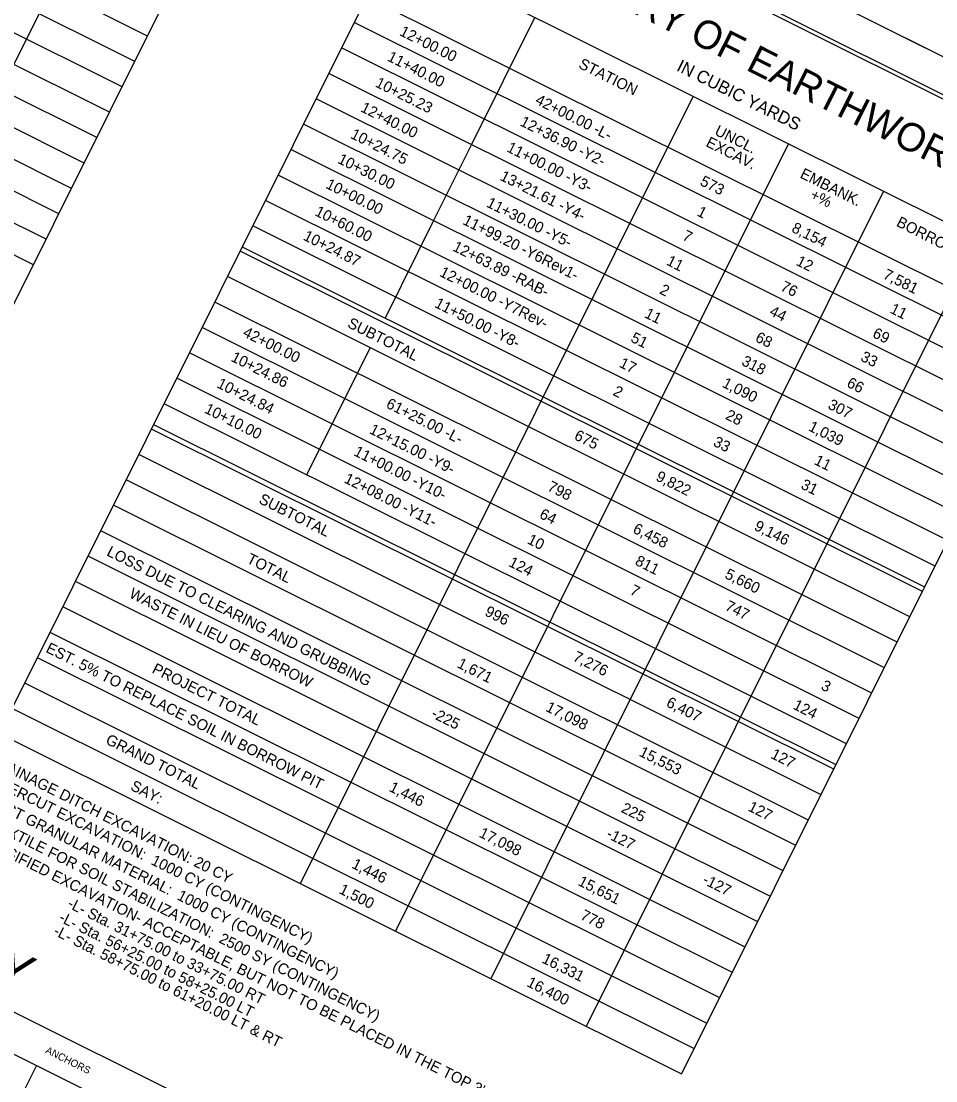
# Model space of a CAD drawing. Extents: x 1771109 to 1774678, y 884436 to 887277.
# Drawn here: x 1773772 to 1774376, y 885998 to 886698 of the extents above; entities that cross this region are included whole.
import ezdxf

# ---------------------------------------------------------------- set-up
doc = ezdxf.new("R2010")
doc.units = 0
for name, color, linetype in [('Sheet Border Standard 30in CELL', 7, 'Continuous'), ('Sheet Cutting Line CELL', 7, 'Continuous'), ('Sheet Plot Border Inside CELL', 7, 'Continuous'), ('Sheet Plot Border Outside CELL', 7, 'Continuous'), ('Sheet Summary Combination CELL', 7, 'Continuous'), ('Sheet Summary Combination Grid CELL', 7, 'Continuous'), ('Sheet Summary Earthwork CELL', 7, 'Continuous'), ('Sheet Summary Guardrail CELL', 7, 'Continuous')]:
    doc.layers.add(name, color=color, linetype=linetype)

msp = doc.modelspace()

# ---------------------------------------------------------------- linework, layer by layer
at = {"layer": 'Sheet Border Standard 30in CELL'}
msp.add_lwpolyline([(1774652.12, 886510.92), (1773309.73, 887180.24), (1772841.21, 886240.56), (1774183.6, 885571.25)], close=True, dxfattribs=at)
at = {"layer": 'Sheet Cutting Line CELL'}
msp.add_line((1774678.49, 886525.71), (1773171.43, 887277.13), dxfattribs=at)
at = {"layer": 'Sheet Plot Border Inside CELL'}
msp.add_lwpolyline([(1774664.45, 886507.63), (1773173.05, 887251.23), (1772702.25, 886307), (1774193.65, 885563.39)], close=True, dxfattribs=at)
at = {"layer": 'Sheet Plot Border Outside CELL'}
msp.add_lwpolyline([(1774678.49, 886525.71), (1773171.43, 887277.13), (1772680.6, 886292.7), (1774187.66, 885541.29)], close=True, dxfattribs=at)
at = {"layer": 'Sheet Summary Combination CELL'}
for p, q in [((1774153.09, 886679.28), (1774153.09, 886679.28)), ((1774161.42, 886674.96), (1774161.42, 886674.96)), ((1774173.7, 886669.17), (1774173.7, 886669.17)), ((1774181.15, 886665.29), (1774181.15, 886665.29))]:
    msp.add_line(p, q, dxfattribs=at)
at = {"layer": 'Sheet Summary Combination Grid CELL'}
for p, q in [((1773287.9, 886970.94), (1773854.86, 886688.25)), ((1773279.53, 886954.16), (1773846.49, 886671.47)), ((1773271.17, 886937.38), (1773838.13, 886654.69)), ((1773262.8, 886920.6), (1773829.76, 886637.91)), ((1773254.44, 886903.82), (1773821.4, 886621.13)), ((1773246.07, 886887.04), (1773813.03, 886604.35)), ((1773237.7, 886870.26), (1773804.66, 886587.57)), ((1773229.34, 886853.48), (1773796.3, 886570.79)), ((1773220.97, 886836.7), (1773787.93, 886554.01)), ((1773212.6, 886819.92), (1773779.56, 886537.23)), ((1773833.6, 886803.61), (1773607.71, 886350.55)), ((1773896.69, 886772.15), (1773670.8, 886319.09)), ((1774016.48, 886747.48), (1773757.12, 886227.3)), ((1774016.48, 886747.48), (1774467.11, 886522.79)), ((1773999.74, 886713.92), (1774450.38, 886489.23)), ((1774110.91, 886700.39), (1774069.08, 886616.49)), ((1773991.38, 886697.14), (1774442.01, 886472.45)), ((1773983.01, 886680.36), (1774433.65, 886455.67)), ((1773974.64, 886663.58), (1774425.28, 886438.89)), ((1774215.28, 886648.36), (1773955.92, 886128.18)), ((1773966.28, 886646.8), (1774416.91, 886422.11)), ((1773957.91, 886630.02), (1774408.55, 886405.33)), ((1774278.24, 886616.97), (1774018.88, 886096.79)), ((1774069.08, 886616.49), (1774043.98, 886566.15)), ((1773949.54, 886613.24), (1774400.18, 886388.55)), ((1773941.18, 886596.46), (1774391.81, 886371.77)), ((1774341.2, 886585.57), (1774081.84, 886065.4)), ((1773932.81, 886579.68), (1774383.45, 886354.99)), ((1773924.44, 886562.9), (1774375.08, 886338.21)), ((1774043.98, 886566.15), (1774011.89, 886501.79)), ((1774404.15, 886554.18), (1774144.79, 886034.01)), ((1773917.46, 886548.88), (1774368.09, 886324.19)), ((1773916.08, 886546.12), (1774366.72, 886321.43)), ((1773907.71, 886529.34), (1774358.35, 886304.65)), ((1774467.11, 886522.79), (1774207.75, 886002.62)), ((1773899.35, 886512.56), (1774349.98, 886287.87)), ((1773890.98, 886495.78), (1774341.62, 886271.09)), ((1773882.61, 886479), (1774333.25, 886254.31)), ((1774002.15, 886482.25), (1773960.32, 886398.35)), ((1773874.25, 886462.22), (1774324.88, 886237.53)), ((1773865.88, 886445.44), (1774316.52, 886220.75)), ((1773857.51, 886428.66), (1774308.15, 886203.97)), ((1773858.97, 886431.58), (1774309.61, 886206.9)), ((1773849.15, 886411.88), (1774299.78, 886187.19)), ((1773840.78, 886395.1), (1774291.42, 886170.41)), ((1773832.41, 886378.32), (1774283.05, 886153.63)), ((1773824.05, 886361.54), (1774274.68, 886136.85)), ((1773815.68, 886344.76), (1774266.32, 886120.07)), ((1773807.32, 886327.98), (1774257.95, 886103.3)), ((1773798.95, 886311.2), (1774249.59, 886086.52)), ((1773790.58, 886294.42), (1774241.22, 886069.74)), ((1773782.22, 886277.64), (1774232.85, 886052.96)), ((1773773.85, 886260.86), (1774224.49, 886036.18)), ((1773765.48, 886244.08), (1774216.12, 886019.4)), ((1773757.12, 886227.3), (1774207.75, 886002.62))]:
    msp.add_line(p, q, dxfattribs=at)
at = {"layer": 'Sheet Summary Guardrail CELL'}
for p, q in [((1772947.61, 886451.91), (1774290, 885782.59)), ((1773928.84, 885934.73), (1773500.7, 886148.2)), ((1773781.62, 886008.13), (1773714.69, 885873.89))]:
    msp.add_line(p, q, dxfattribs=at)

# ---------------------------------------------------------------- texts
at = {"layer": 'Sheet Summary Combination CELL'}
for s, p in [('12+00.00', (1774020.9, 886688.85)), ('11+40.00', (1774012.87, 886672.05)), ('STATION', (1774139.17, 886667.29)), ('10+25.23', (1774004.87, 886654.89)), ('42+00.00 -L-', (1774110.5, 886643.61)), ('12+40.00', (1773995.17, 886638.47)), ('12+36.90 -Y2-', (1774100.46, 886629.2)), ('10+24.75', (1773988.54, 886620.95)), ('UNCL.', (1774229, 886623.16)), ('11+00.00 -Y3-', (1774091.68, 886612.1)), ('EXCAV.', (1774223.21, 886615.5)), ('10+30.00', (1773980.04, 886604.48)), ('13+21.61 -Y4-', (1774087.24, 886593.23)), ('573', (1774219.35, 886589.85)), ('EMBANK.', (1774285.42, 886594.79)), ('10+00.00', (1773972.14, 886587.93)), ('+%', (1774291.99, 886580.92)), ('10+60.00', (1773964.94, 886569.91)), ('11+30.00 -Y5-', (1774078.32, 886575.59)), ('1', (1774217.36, 886569.72)), ('11+99.20 -Y6Rev1-', (1774062.62, 886564.09)), ('BORROW', (1774349.02, 886562.82)), ('8,154', (1774279.82, 886559.03)), ('10+24.87', (1773957.31, 886553.75)), ('7', (1774207.73, 886553.85)), ('12+63.89 -RAB-', (1774055.97, 886546.62)), ('11', (1774197.18, 886537.23)), ('12', (1774282.84, 886537.08)), ('12+00.00 -Y7Rev-', (1774047.3, 886529.83)), ('7,581', (1774340.24, 886528.3)), ('76', (1774272.5, 886520.35)), ('2', (1774192.66, 886518.2)), ('11+50.00 -Y8-', (1774044.01, 886509.26)), ('11', (1774182.7, 886502.5)), ('44', (1774265.14, 886503.96)), ('11', (1774344.83, 886505.56)), ('SUBTOTAL', (1773986.46, 886496.07)), ('42+00.00 ', (1773917.4, 886490.08)), ('51', (1774173.59, 886486.46)), ('68', (1774255.86, 886486.7)), ('69', (1774333.28, 886489.44)), ('10+24.86', (1773909.59, 886473.67)), ('318', (1774246.76, 886471.1)), ('33', (1774325.4, 886473.92)), ('17', (1774165.99, 886469.74)), ('66', (1774316.26, 886456.7)), ('10+24.84', (1773900.25, 886456.25)), ('2', (1774161.88, 886451.18)), ('1,090', (1774234.03, 886456.55)), ('61+25.00 -L-', (1774012.02, 886442.92)), ('10+10.00', (1773892.02, 886439.54)), ('307', (1774303.81, 886442.31)), ('28', (1774236.13, 886435.38)), ('12+15.00 -Y9-', (1774000.99, 886425.95)), ('675', (1774136.26, 886421.96)), ('1,039', (1774290.95, 886427.82)), ('33', (1774228.06, 886417.73)), ('11+00.00 -Y10-', (1773990.67, 886411.39)), ('11', (1774294.78, 886405.51)), ('9,822', (1774190.15, 886394.84)), ('12+08.00 -Y11-', (1773984.23, 886393.43)), ('798', (1774118.58, 886388.19)), ('31', (1774285.94, 886389.49)), ('SUBTOTAL', (1773927.9, 886379.88)), ('64', (1774113.27, 886370.01)), ('6,458', (1774175, 886360.34)), ('9,146', (1774255.11, 886362.18)), ('10', (1774105.25, 886353.17)), ('LOSS DUE TO CLEARING AND GRUBBING', (1773827.51, 886345.24)), ('TOTAL', (1773919.95, 886340.42)), ('124', (1774092.94, 886338.21)), ('811', (1774176.45, 886339.13)), ('5,660', (1774235.71, 886330.38)), ('WASTE IN LIEU OF BORROW', (1773842.34, 886317.57)), ('7', (1774173.04, 886319.7)), ('747', (1774235.9, 886309.3)), ('996', (1774077.2, 886305.71)), ('EST. 5% TO REPLACE SOIL IN BORROW PIT', (1773787.34, 886281.47)), ('7,276', (1774135.41, 886275.84)), ('PROJECT TOTAL', (1773857.47, 886267.8)), ('1,671', (1774058.96, 886271.3)), ('3', (1774299.26, 886256.77)), ('17,098', (1774117.4, 886242.58)), ('6,407', (1774197.04, 886245.6)), ('124', (1774280.77, 886243.93)), ('-225', (1774041.81, 886238.44)), ('GRAND TOTAL', (1773826.8, 886221.01)), ('15,553', (1774179.1, 886212.91)), ('DRAINAGE DITCH EXCAVATION: 20 CY', (1773748.72, 886208.65)), ('127', (1774266.11, 886211.51)), ('UNDERCUT EXCAVATION:  1000 CY (CONTINGENCY)', (1773743.53, 886198.23)), ('SELECT GRANULAR MATERIAL:  1000 CY (CONTINGENCY)', (1773737.73, 886186.59)), ('SAY:', (1773843.18, 886190.47)), ('1,446', (1774014.03, 886189.63)), ('GEOTEXTILE FOR SOIL STABILIZATION:  2500 SY (CONTINGENCY)', (1773731.93, 886174.96)), ('225', (1774167.32, 886175.82)), ('127', (1774251.07, 886176.75)), ("UNCLASSIFIED EXCAVATION- ACCEPTABLE, BUT NOT TO BE PLACED IN THE TOP 3' OF EMBANKMENT OR BACKFILL:  400 CY", (1773725.9, 886163.89)), ('17,098', (1774073.38, 886159.44)), ('-127', (1774157.45, 886158.94)), ('1,446', (1773989.33, 886138.96)), ('1,500', (1773980.93, 886122.15)), ('15,651', (1774138.76, 886127.49)), ('-127', (1774221, 886128.62)), ('-L- Sta. 31+75.00 to 33+75.00 RT', (1773801.61, 886112.88)), ('-L- Sta. 56+25.00 to 58+25.00 LT', (1773795.89, 886103.71)), ('778', (1774140.33, 886105.1)), ('-L- Sta. 58+75.00 to 61+20.00 LT & RT', (1773792.31, 886094.79)), ('16,331', (1774114.91, 886076.43)), ('16,400', (1774104.91, 886060.79))]:
    msp.add_text(s, height=7.2, rotation=333.30813, dxfattribs=at).set_placement(p)
at = {"layer": 'Sheet Summary Earthwork CELL'}
for s, height, p in [('SUMMARY OF EARTHWORK', 18.7499, (1774091.42, 886745.48)), ('IN CUBIC YARDS', 8.2498, (1774203.87, 886665.52))]:
    msp.add_text(s, height=height, rotation=333.30813, dxfattribs=at).set_placement(p)
at = {"layer": 'Sheet Summary Guardrail CELL'}
for s, height, p in [('GUARDRAIL SUMMARY', 24.9999, (1773436, 886222.81)), ('ANCHORS', 4.8, (1773787.2, 886016.64))]:
    msp.add_text(s, height=height, rotation=333.49928, dxfattribs=at).set_placement(p)

doc.saveas('drawing.dxf')
